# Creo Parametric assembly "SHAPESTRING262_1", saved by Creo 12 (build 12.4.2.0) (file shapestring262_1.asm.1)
Units: Custom; MM, KILOGRAM, SECS

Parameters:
  PTC_WM_ITERATION = "0"
  PTC_WM_VERSION = "-.0"
  PTC_WM_LIFECYCLE_STATE = "In Work"
  PTC_WM_LIFECYCLE = "MO_CADDocument"
  PTC_WM_CREATED_BY = "Maximilian Roepper (Z0017RMS: MO)"
  PTC_WM_CREATED_ON = "18-Sep-26 11:36:42 AM"
  PTC_WM_MODIFIED_BY = "Maximilian Roepper (Z0017RMS: MO)"
  PTC_WM_MODIFIED_ON = "18-Sep-26 11:36:46 AM"
  PDMLINKNUMBER = "PDM000071455289"
  PTC_WM_NUMBER = "PDM000071455289"

Other parameters: WEIGHT, WEIGHT_FACTOR, WEIGHT_ADD, MC_ERRORS, SUPPLIER

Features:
  1. coordinate system
  2. imported feature
  3. component "SHAPESTRING003_1"
  4. component "SHAPESTRING260_1"
  5. component "SHAPESTRING261_1"

Other named items: DRW_VIEW_ORG, ROUGH-GROB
